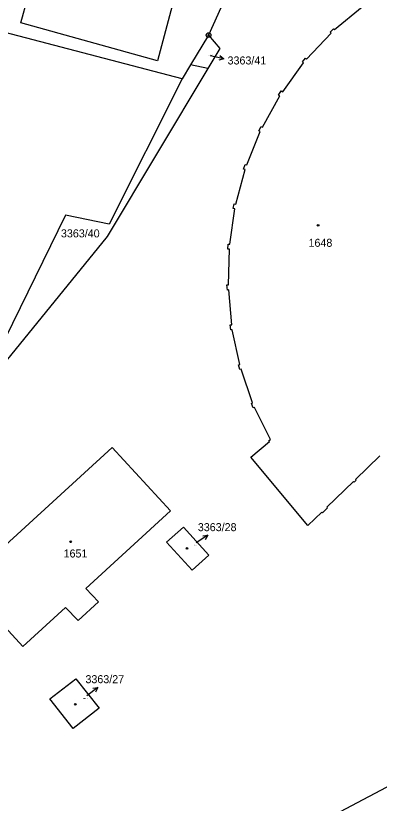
# Model space of a CAD drawing. Extents: x -755819 to -753140, y -1169796 to -1166000.
# Drawn here: x -754826.5 to -754749.4, y -1167784.6 to -1167617.5 of the extents above; entities that cross this region are included whole.
import ezdxf

# ---------------------------------------------------------------- set-up
doc = ezdxf.new("R2010")
doc.units = 0
for name, color, linetype in [('Vrstva 1', 7, 'Continuous'), ('Vrstva 16', 7, 'Continuous'), ('Vrstva 18', 7, 'Continuous'), ('Vrstva 19', 7, 'Continuous'), ('Vrstva 24', 7, 'Continuous'), ('Vrstva 25', 7, 'Continuous'), ('Vrstva 6', 7, 'Continuous')]:
    doc.layers.add(name, color=color, linetype=linetype)

msp = doc.modelspace()

# ---------------------------------------------------------------- linework, layer by layer
at = {"layer": 'Vrstva 1'}
for p, q in [((-754825.44, -1167618.96), (-754815.65, -1167583.29)), ((-754771.2, -1167589.18), (-754785.59, -1167621.57)), ((-754793.29, -1167615.38), (-754796.46, -1167627)), ((-754758.85, -1167620.41), (-754753.01, -1167615.59)), ((-754791.23, -1167630.86), (-754841.65, -1167617.66)), ((-754796.46, -1167627), (-754825.44, -1167618.96)), ((-754759.79, -1167620.92), (-754759.05, -1167620.21)), ((-754759.59, -1167621.13), (-754759.79, -1167620.92)), ((-754759.05, -1167620.21), (-754758.85, -1167620.41)), ((-754785.59, -1167621.57), (-754789.42, -1167627.87)), ((-754764.79, -1167626.66), (-754759.59, -1167621.13)), ((-754769.87, -1167633.62), (-754765.44, -1167627.45)), ((-754765.66, -1167627.28), (-754765.03, -1167626.47)), ((-754765.44, -1167627.45), (-754765.66, -1167627.28)), ((-754765.03, -1167626.47), (-754764.79, -1167626.66)), ((-754789.42, -1167627.87), (-754791.23, -1167630.86)), ((-754791.23, -1167630.86), (-754806.67, -1167661.67)), ((-754770.73, -1167634.3), (-754770.16, -1167633.43)), ((-754770.45, -1167634.48), (-754770.73, -1167634.3)), ((-754770.16, -1167633.43), (-754769.87, -1167633.62)), ((-754774.15, -1167641.12), (-754770.45, -1167634.48)), ((-754774.91, -1167641.92), (-754774.46, -1167640.97)), ((-754774.46, -1167640.97), (-754774.15, -1167641.12)), ((-754777.51, -1167649.12), (-754774.62, -1167642.06)), ((-754774.62, -1167642.06), (-754774.91, -1167641.92)), ((-754778.15, -1167650.04), (-754777.81, -1167649.02)), ((-754777.81, -1167649.02), (-754777.51, -1167649.12)), ((-754779.8, -1167657.44), (-754777.85, -1167650.13)), ((-754777.85, -1167650.13), (-754778.15, -1167650.04)), ((-754780.36, -1167658.41), (-754780.13, -1167657.36)), ((-754780.13, -1167657.36), (-754779.8, -1167657.44)), ((-754781.09, -1167665.94), (-754780.03, -1167658.48)), ((-754780.03, -1167658.48), (-754780.36, -1167658.41)), ((-754815.97, -1167659.76), (-754834.99, -1167698.58)), ((-754806.67, -1167661.67), (-754815.97, -1167659.76)), ((-754781.49, -1167666.98), (-754781.43, -1167665.92)), ((-754781.43, -1167665.92), (-754781.09, -1167665.94)), ((-754781.17, -1167667), (-754781.49, -1167666.98)), ((-754781.36, -1167674.59), (-754781.17, -1167667)), ((-754781.69, -1167674.61), (-754781.36, -1167674.59)), ((-754781.61, -1167675.69), (-754781.69, -1167674.61)), ((-754781.31, -1167675.67), (-754781.61, -1167675.69)), ((-754780.67, -1167683.05), (-754781.31, -1167675.67)), ((-754780.99, -1167683.09), (-754780.67, -1167683.05)), ((-754780.86, -1167684.14), (-754780.99, -1167683.09)), ((-754780.56, -1167684.1), (-754780.86, -1167684.14)), ((-754778.96, -1167691.48), (-754780.56, -1167684.1)), ((-754779.24, -1167691.55), (-754778.96, -1167691.48)), ((-754778.98, -1167692.55), (-754779.24, -1167691.55)), ((-754778.67, -1167692.47), (-754778.98, -1167692.55)), ((-754776.24, -1167699.63), (-754778.67, -1167692.47)), ((-754776.51, -1167699.74), (-754776.24, -1167699.63)), ((-754776.11, -1167700.7), (-754776.51, -1167699.74)), ((-754775.83, -1167700.59), (-754776.11, -1167700.7)), ((-754772.47, -1167707.44), (-754775.83, -1167700.59)), ((-754776.6, -1167711.16), (-754772.67, -1167707.85)), ((-754772.79, -1167707.59), (-754772.47, -1167707.44)), ((-754772.67, -1167707.85), (-754772.79, -1167707.59)), ((-754837.41, -1167737.8), (-754806.05, -1167709.09)), ((-754806.05, -1167709.09), (-754793.71, -1167722.59)), ((-754764.56, -1167725.64), (-754776.6, -1167711.16)), ((-754749.24, -1167710.88), (-754754.39, -1167715.89)), ((-754754.27, -1167716.02), (-754754.73, -1167716.46)), ((-754754.39, -1167715.89), (-754754.27, -1167716.02)), ((-754754.85, -1167716.33), (-754760.49, -1167721.81)), ((-754754.73, -1167716.46), (-754754.85, -1167716.33)), ((-754793.71, -1167722.59), (-754811.62, -1167739.04)), ((-754761.57, -1167722.81), (-754764.56, -1167725.64)), ((-754761.42, -1167722.96), (-754761.57, -1167722.81)), ((-754760.37, -1167721.94), (-754761.42, -1167722.96)), ((-754760.49, -1167721.81), (-754760.37, -1167721.94)), ((-754794.51, -1167729.19), (-754790.94, -1167725.99)), ((-754790.94, -1167725.99), (-754785.51, -1167731.93)), ((-754789.07, -1167735.12), (-754794.51, -1167729.19)), ((-754785.51, -1167731.93), (-754789.07, -1167735.12)), ((-754825.03, -1167751.37), (-754837.41, -1167737.8)), ((-754811.62, -1167739.04), (-754808.98, -1167741.87)), ((-754808.98, -1167741.87), (-754813.29, -1167745.82)), ((-754815.97, -1167743.04), (-754825.03, -1167751.37)), ((-754813.29, -1167745.82), (-754815.97, -1167743.04)), ((-754819.27, -1167762.47), (-754813.79, -1167758.19)), ((-754813.79, -1167758.19), (-754808.8, -1167764.46)), ((-754814.33, -1167768.77), (-754819.27, -1167762.47)), ((-754808.8, -1167764.46), (-754814.33, -1167768.77)), ((-754757.58, -1167786.36), (-754728.21, -1167770.8))]:
    msp.add_line(p, q, dxfattribs=at)
at = {"layer": 'Vrstva 16'}
for p, q in [((-754782.34, -1167626.6), (-754785.28, -1167625.99)), ((-754785.72, -1167727.75), (-754788.25, -1167729.36)), ((-754809.07, -1167760.02), (-754811.45, -1167761.84))]:
    msp.add_line(p, q, dxfattribs=at)
for points in [[(-754783.22, -1167625.91), (-754782.34, -1167626.6), (-754783.42, -1167626.89)], [(-754786.83, -1167727.87), (-754785.72, -1167727.75), (-754786.29, -1167728.71)], [(-754810.16, -1167760.23), (-754809.07, -1167760.02), (-754809.56, -1167761.03)]]:
    msp.add_lwpolyline(points, dxfattribs=at)
at = {"layer": 'Vrstva 24'}
for radius in [0.5, 0.1]:
    msp.add_circle((-754785.59, -1167621.57), radius, dxfattribs=at)
at = {"layer": 'Vrstva 25'}
for centre in [(-754762.34, -1167661.94), (-754814.85, -1167729.13), (-754790.16, -1167730.54), (-754813.88, -1167763.62)]:
    msp.add_circle(centre, 0.175, dxfattribs=at)
at = {"layer": 'Vrstva 6'}
for p, q in [((-754785.59, -1167621.57), (-754783.24, -1167624.41)), ((-754783.24, -1167624.41), (-754785.74, -1167628.63)), ((-754785.74, -1167628.63), (-754807.14, -1167664.31)), ((-754785.74, -1167628.63), (-754789.42, -1167627.87)), ((-754807.14, -1167664.31), (-754834.99, -1167698.58))]:
    msp.add_line(p, q, dxfattribs=at)

# ---------------------------------------------------------------- texts
at = {"layer": 'Vrstva 16'}
for s, p in [('3363/41', (-754781.57, -1167627.8)), ('3363/28', (-754787.88, -1167726.87)), ('3363/27', (-754811.73, -1167759.14))]:
    msp.add_text(s, height=1.7, dxfattribs=at).set_placement(p)
at = {"layer": 'Vrstva 18'}
for s, height, p in [('3363/41', 0.2, (-754785.69, -1167625.9)), ('3363/40', 1.7, (-754816.93, -1167664.51))]:
    msp.add_text(s, height=height, dxfattribs=at).set_placement(p)
at = {"layer": 'Vrstva 19'}
for s, height, p in [('1648', 1.7, (-754764.39, -1167666.51)), ('1651', 1.7, (-754816.37, -1167732.46)), ('3363/28', 0.2, (-754789.09, -1167729.91)), ('3363/27', 0.2, (-754812.27, -1167762.49))]:
    msp.add_text(s, height=height, dxfattribs=at).set_placement(p)

doc.saveas('drawing.dxf')
